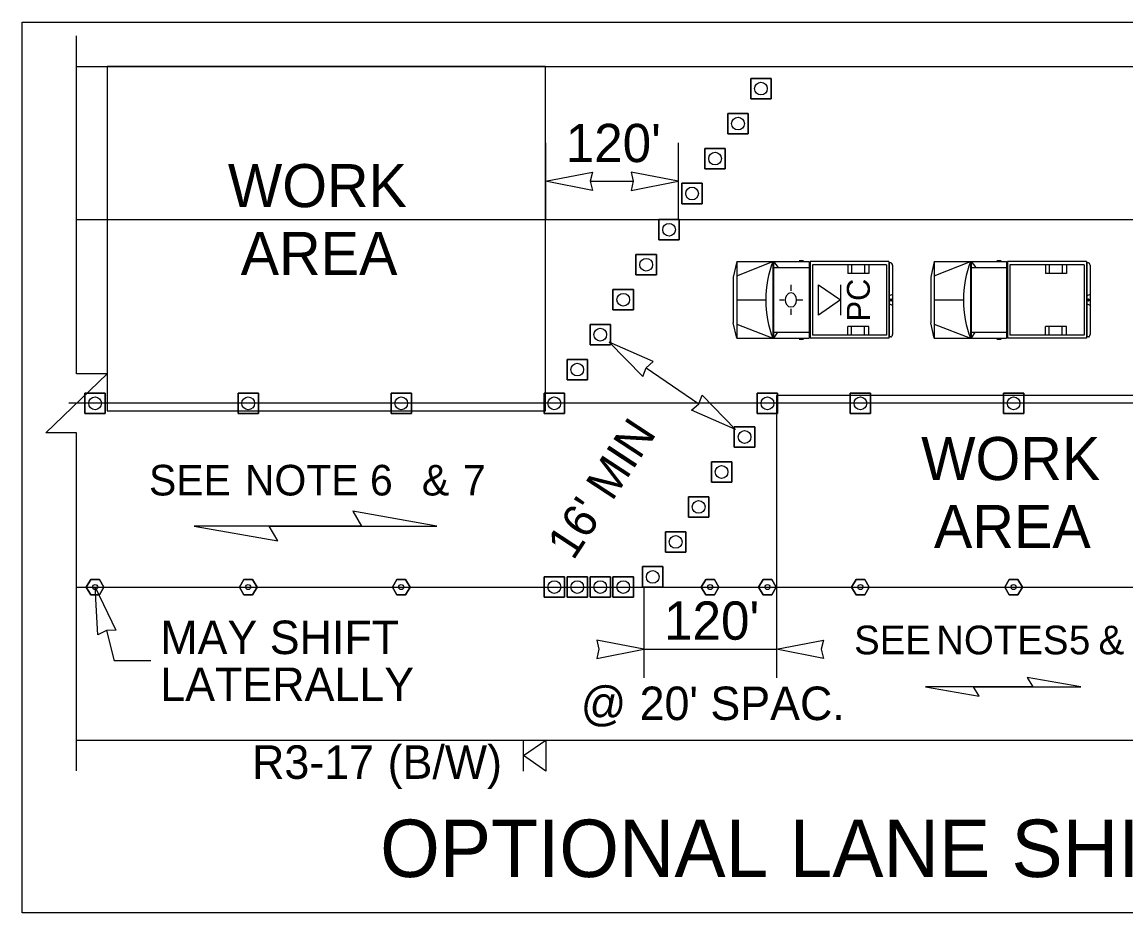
# Model space of a CAD drawing. Extents: x 99999.1 to 100095.7, y 99995 to 100010.7.
# Drawn here: x 100045.162 to 100047.47, y 100003.505 to 100005.366 of the extents above; entities that cross this region are included whole.
import ezdxf

# ---------------------------------------------------------------- set-up
doc = ezdxf.new("R2010")
doc.units = 0
for name, color, linetype in [('RD_ED_ShoulderPavedEdge', 7, 'Continuous'), ('RD_MK_LineEdgeWhite', 7, 'Continuous'), ('RD_MK_LineSkipCenter', 7, 'Continuous'), ('SH_DE_DetailHeading2Text', 7, 'Continuous'), ('SH_TI_Tables', 7, 'Continuous'), ('TR_WZ_MotoristVehicle', 7, 'Continuous'), ('TR_WZ_PortableSignMountBlk-Wht', 7, 'Continuous'), ('TR_WZ_TrafficCone', 7, 'Continuous'), ('TR_WZ_TubularMarker', 7, 'Continuous'), ('TR_WZ_WorkZoneDetails', 7, 'Continuous'), ('TR_WZ_WorkZoneTextCurrent', 7, 'Continuous')]:
    doc.layers.add(name, color=color, linetype=linetype)

msp = doc.modelspace()

# ---------------------------------------------------------------- linework, layer by layer
at = {"layer": 'RD_ED_ShoulderPavedEdge'}
for p, q in [((100045.2759, 100005.2735), (100049.1933, 100005.2735)), ((100045.2759, 100003.8655), (100049.1933, 100003.8655))]:
    msp.add_line(p, q, dxfattribs=at)
at = {"layer": 'RD_MK_LineEdgeWhite'}
for p, q in [((100045.2759, 100004.9535), (100049.1933, 100004.9535)), ((100045.2759, 100004.1855), (100049.1933, 100004.1855))]:
    msp.add_line(p, q, dxfattribs=at)
at = {"layer": 'RD_MK_LineSkipCenter'}
msp.add_lwpolyline([(100049.1767, 100004.5695), (100045.2594, 100004.5695)], dxfattribs=at)
at = {"layer": 'SH_TI_Tables'}
msp.add_lwpolyline([(100045.1619, 100005.3662), (100049.3073, 100005.3662), (100049.3073, 100003.5045), (100045.1619, 100003.5045)], close=True, dxfattribs=at)
at = {"layer": 'TR_WZ_MotoristVehicle'}
for p, q in [((100046.656, 100004.8655), (100046.6486, 100004.8332)), ((100046.656, 100004.8655), (100046.656, 100004.7055)), ((100046.656, 100004.8655), (100046.8071, 100004.8655)), ((100046.656, 100004.8362), (100046.7316, 100004.8655)), ((100046.7316, 100004.8655), (100046.7316, 100004.7055)), ((100046.7329, 100004.8655), (100046.7329, 100004.7055)), ((100046.7329, 100004.8655), (100046.7425, 100004.8531)), ((100046.7329, 100004.8531), (100046.8071, 100004.8531)), ((100046.7865, 100004.8677), (100046.7956, 100004.8677)), ((100046.8071, 100004.8655), (100046.8071, 100004.7055)), ((100046.9739, 100004.8655), (100046.8093, 100004.8655)), ((100046.8093, 100004.8655), (100046.8093, 100004.7055)), ((100046.9692, 100004.8591), (100046.814, 100004.8591)), ((100046.814, 100004.8591), (100046.814, 100004.7119)), ((100046.8882, 100004.8591), (100046.8882, 100004.8407)), ((100046.8961, 100004.8591), (100046.8961, 100004.8407)), ((100046.9233, 100004.8591), (100046.9233, 100004.8407)), ((100046.9321, 100004.8591), (100046.9321, 100004.8407)), ((100046.9692, 100004.8591), (100046.9692, 100004.7119)), ((100046.9739, 100004.8655), (100046.9739, 100004.7055)), ((100046.978, 100004.8629), (100046.9744, 100004.8629)), ((100046.9744, 100004.8629), (100046.9744, 100004.7081)), ((100046.9816, 100004.858), (100046.9816, 100004.713)), ((100047.069, 100004.8655), (100047.0616, 100004.8332)), ((100047.069, 100004.8655), (100047.069, 100004.7055)), ((100047.069, 100004.8655), (100047.2201, 100004.8655)), ((100047.069, 100004.8362), (100047.1446, 100004.8655)), ((100047.1446, 100004.8655), (100047.1446, 100004.7055)), ((100047.1459, 100004.8655), (100047.1459, 100004.7055)), ((100047.1459, 100004.8655), (100047.1556, 100004.8531)), ((100047.1459, 100004.8531), (100047.2201, 100004.8531)), ((100047.1995, 100004.8677), (100047.2086, 100004.8677)), ((100047.2201, 100004.8655), (100047.2201, 100004.7055)), ((100047.3869, 100004.8655), (100047.2223, 100004.8655)), ((100047.2223, 100004.8655), (100047.2223, 100004.7055)), ((100047.3822, 100004.8591), (100047.227, 100004.8591)), ((100047.227, 100004.8591), (100047.227, 100004.7119)), ((100047.3012, 100004.8591), (100047.3012, 100004.8407)), ((100047.3091, 100004.8591), (100047.3091, 100004.8407)), ((100047.3364, 100004.8591), (100047.3364, 100004.8407)), ((100047.3451, 100004.8591), (100047.3451, 100004.8407)), ((100047.3822, 100004.8591), (100047.3822, 100004.7119)), ((100047.3869, 100004.8655), (100047.3869, 100004.7055)), ((100047.391, 100004.8629), (100047.3875, 100004.8629)), ((100047.3875, 100004.8629), (100047.3875, 100004.7081)), ((100047.3946, 100004.858), (100047.3946, 100004.713)), ((100046.6486, 100004.8332), (100046.6486, 100004.7378)), ((100046.9321, 100004.8407), (100046.8882, 100004.8407)), ((100047.0616, 100004.8332), (100047.0616, 100004.7378)), ((100047.3451, 100004.8407), (100047.3012, 100004.8407)), ((100046.7692, 100004.8172), (100046.7692, 100004.8043)), ((100046.656, 100004.7855), (100046.7167, 100004.7855)), ((100046.7451, 100004.7856), (100046.7552, 100004.7856)), ((100046.7805, 100004.7852), (100046.7805, 100004.7852)), ((100046.7939, 100004.7849), (100046.782, 100004.7852)), ((100046.9816, 100004.7968), (100046.9744, 100004.7938)), ((100046.9797, 100004.7855), (100046.9764, 100004.7855)), ((100046.978, 100004.7877), (100046.978, 100004.7832)), ((100047.069, 100004.7855), (100047.1297, 100004.7855)), ((100047.3946, 100004.7968), (100047.3875, 100004.7938)), ((100047.3927, 100004.7855), (100047.3894, 100004.7855)), ((100047.391, 100004.7877), (100047.391, 100004.7832)), ((100046.7698, 100004.7547), (100046.7695, 100004.7668)), ((100046.9816, 100004.7742), (100046.9744, 100004.7772)), ((100047.3946, 100004.7742), (100047.3875, 100004.7772)), ((100046.656, 100004.7055), (100046.6486, 100004.7378)), ((100046.656, 100004.7348), (100046.7316, 100004.7055)), ((100047.069, 100004.7055), (100047.0616, 100004.7378)), ((100047.069, 100004.7348), (100047.1446, 100004.7055)), ((100046.7329, 100004.7179), (100046.8071, 100004.7179)), ((100046.7409, 100004.7179), (100046.7329, 100004.7055)), ((100046.9692, 100004.7119), (100046.814, 100004.7119)), ((100046.8882, 100004.7119), (100046.8882, 100004.7303)), ((100046.9321, 100004.7303), (100046.8882, 100004.7303)), ((100046.8961, 100004.7119), (100046.8961, 100004.7303)), ((100046.9233, 100004.7119), (100046.9233, 100004.7303)), ((100046.9321, 100004.7119), (100046.9321, 100004.7303)), ((100047.1459, 100004.7179), (100047.2201, 100004.7179)), ((100047.1539, 100004.7179), (100047.1459, 100004.7055)), ((100047.3822, 100004.7119), (100047.227, 100004.7119)), ((100047.3012, 100004.7119), (100047.3012, 100004.7303)), ((100047.3451, 100004.7303), (100047.3012, 100004.7303)), ((100047.3091, 100004.7119), (100047.3091, 100004.7303)), ((100047.3364, 100004.7119), (100047.3364, 100004.7303)), ((100047.3451, 100004.7119), (100047.3451, 100004.7303)), ((100046.656, 100004.7055), (100046.8071, 100004.7055)), ((100046.7865, 100004.7032), (100046.7956, 100004.7032)), ((100046.9739, 100004.7055), (100046.8093, 100004.7055)), ((100046.978, 100004.7081), (100046.9744, 100004.7081)), ((100047.069, 100004.7055), (100047.2201, 100004.7055)), ((100047.1995, 100004.7032), (100047.2086, 100004.7032)), ((100047.3869, 100004.7055), (100047.2223, 100004.7055)), ((100047.391, 100004.7081), (100047.3875, 100004.7081))]:
    msp.add_line(p, q, dxfattribs=at)
for centre, major_axis, start_param, end_param in [((100046.8395, 100004.7855), (0, -0.1679), 4.215667, 5.208926), ((100046.978, 100004.858), (0, 0.00488), 4.712389, 6.283185), ((100047.2526, 100004.7855), (0, -0.1679), 4.215667, 5.208926), ((100047.391, 100004.858), (0, 0.00488), 4.712389, 6.283185), ((100046.978, 100004.713), (0, -0.00488), 0, 1.570796), ((100047.391, 100004.713), (0, -0.00488), 0, 1.570796)]:
    msp.add_ellipse(centre, major_axis=major_axis, ratio=0.73155, start_param=start_param, end_param=end_param, dxfattribs=at)
for centre, major_axis in [((100046.7692, 100004.7855), (0, 0.0154)), ((100046.978, 100004.7855), (0, 0.00225)), ((100047.391, 100004.7855), (0, 0.00225))]:
    msp.add_ellipse(centre, major_axis=major_axis, ratio=0.73155, dxfattribs=at)
at = {"layer": 'TR_WZ_PortableSignMountBlk-Wht'}
for p, q in [((100046.8731, 100004.8174), (100046.8731, 100004.7534)), ((100046.2103, 100003.8011), (100046.2103, 100003.8655))]:
    msp.add_line(p, q, dxfattribs=at)
for points in [[(100046.8731, 100004.7855), (100046.8271, 100004.7534), (100046.8271, 100004.8174)], [(100046.2103, 100003.8333), (100046.2565, 100003.8655), (100046.2565, 100003.8011)]]:
    msp.add_lwpolyline(points, close=True, dxfattribs=at)
at = {"layer": 'TR_WZ_TrafficCone'}
for points in [[(100046.6853, 100005.2484), (100046.7279, 100005.2484), (100046.7279, 100005.2058), (100046.6853, 100005.2058), (100046.6853, 100005.2484)], [(100046.6853, 100005.2058), (100046.7279, 100005.2058), (100046.7279, 100005.2484), (100046.6853, 100005.2484), (100046.6853, 100005.2058)], [(100046.6373, 100005.1754), (100046.6799, 100005.1754), (100046.6799, 100005.1327), (100046.6373, 100005.1327), (100046.6373, 100005.1754)], [(100046.6373, 100005.1327), (100046.6799, 100005.1327), (100046.6799, 100005.1754), (100046.6373, 100005.1754), (100046.6373, 100005.1327)], [(100046.5893, 100005.1023), (100046.6319, 100005.1023), (100046.6319, 100005.0596), (100046.5893, 100005.0596), (100046.5893, 100005.1023)], [(100046.5893, 100005.0596), (100046.6319, 100005.0596), (100046.6319, 100005.1023), (100046.5893, 100005.1023), (100046.5893, 100005.0596)], [(100046.5413, 100005.0292), (100046.5839, 100005.0292), (100046.5839, 100004.9866), (100046.5413, 100004.9866), (100046.5413, 100005.0292)], [(100046.5413, 100004.9866), (100046.5839, 100004.9866), (100046.5839, 100005.0292), (100046.5413, 100005.0292), (100046.5413, 100004.9866)], [(100046.5359, 100004.9535), (100046.4932, 100004.9535), (100046.4932, 100004.9108), (100046.5359, 100004.9108), (100046.5359, 100004.9535)], [(100046.5359, 100004.9108), (100046.4932, 100004.9108), (100046.4932, 100004.9535), (100046.5359, 100004.9535), (100046.5359, 100004.9108)], [(100046.4879, 100004.8804), (100046.4452, 100004.8804), (100046.4452, 100004.8378), (100046.4879, 100004.8378), (100046.4879, 100004.8804)], [(100046.4879, 100004.8378), (100046.4452, 100004.8378), (100046.4452, 100004.8804), (100046.4879, 100004.8804), (100046.4879, 100004.8378)], [(100046.4399, 100004.8074), (100046.3972, 100004.8074), (100046.3972, 100004.7647), (100046.4399, 100004.7647), (100046.4399, 100004.8074)], [(100046.4399, 100004.7647), (100046.3972, 100004.7647), (100046.3972, 100004.8074), (100046.4399, 100004.8074), (100046.4399, 100004.7647)], [(100046.3919, 100004.7343), (100046.3492, 100004.7343), (100046.3492, 100004.6916), (100046.3919, 100004.6916), (100046.3919, 100004.7343)], [(100046.3919, 100004.6916), (100046.3492, 100004.6916), (100046.3492, 100004.7343), (100046.3919, 100004.7343), (100046.3919, 100004.6916)], [(100046.3439, 100004.6612), (100046.3012, 100004.6612), (100046.3012, 100004.6186), (100046.3439, 100004.6186), (100046.3439, 100004.6612)], [(100046.3439, 100004.6186), (100046.3012, 100004.6186), (100046.3012, 100004.6612), (100046.3439, 100004.6612), (100046.3439, 100004.6186)], [(100045.2933, 100004.5908), (100045.3359, 100004.5908), (100045.3359, 100004.5482), (100045.2933, 100004.5482), (100045.2933, 100004.5908)], [(100045.2933, 100004.5482), (100045.3359, 100004.5482), (100045.3359, 100004.5908), (100045.2933, 100004.5908), (100045.2933, 100004.5482)], [(100045.6133, 100004.5908), (100045.6559, 100004.5908), (100045.6559, 100004.5482), (100045.6133, 100004.5482), (100045.6133, 100004.5908)], [(100045.6133, 100004.5482), (100045.6559, 100004.5482), (100045.6559, 100004.5908), (100045.6133, 100004.5908), (100045.6133, 100004.5482)], [(100045.9333, 100004.5908), (100045.9759, 100004.5908), (100045.9759, 100004.5482), (100045.9333, 100004.5482), (100045.9333, 100004.5908)], [(100045.9333, 100004.5482), (100045.9759, 100004.5482), (100045.9759, 100004.5908), (100045.9333, 100004.5908), (100045.9333, 100004.5482)], [(100046.2959, 100004.5908), (100046.2532, 100004.5908), (100046.2532, 100004.5482), (100046.2959, 100004.5482), (100046.2959, 100004.5908)], [(100046.2959, 100004.5482), (100046.2532, 100004.5482), (100046.2532, 100004.5908), (100046.2959, 100004.5908), (100046.2959, 100004.5482)], [(100046.7415, 100004.5908), (100046.6989, 100004.5908), (100046.6989, 100004.5482), (100046.7415, 100004.5482), (100046.7415, 100004.5908)], [(100046.7415, 100004.5482), (100046.6989, 100004.5482), (100046.6989, 100004.5908), (100046.7415, 100004.5908), (100046.7415, 100004.5482)], [(100046.8933, 100004.5908), (100046.9359, 100004.5908), (100046.9359, 100004.5482), (100046.8933, 100004.5482), (100046.8933, 100004.5908)], [(100046.8933, 100004.5482), (100046.9359, 100004.5482), (100046.9359, 100004.5908), (100046.8933, 100004.5908), (100046.8933, 100004.5482)], [(100047.2133, 100004.5908), (100047.2559, 100004.5908), (100047.2559, 100004.5482), (100047.2133, 100004.5482), (100047.2133, 100004.5908)], [(100047.2133, 100004.5482), (100047.2559, 100004.5482), (100047.2559, 100004.5908), (100047.2133, 100004.5908), (100047.2133, 100004.5482)], [(100046.6509, 100004.4778), (100046.6936, 100004.4778), (100046.6936, 100004.5204), (100046.6509, 100004.5204), (100046.6509, 100004.4778)], [(100046.6509, 100004.5204), (100046.6936, 100004.5204), (100046.6936, 100004.4778), (100046.6509, 100004.4778), (100046.6509, 100004.5204)], [(100046.6029, 100004.4047), (100046.6456, 100004.4047), (100046.6456, 100004.4474), (100046.6029, 100004.4474), (100046.6029, 100004.4047)], [(100046.6029, 100004.4474), (100046.6456, 100004.4474), (100046.6456, 100004.4047), (100046.6029, 100004.4047), (100046.6029, 100004.4474)], [(100046.5549, 100004.3316), (100046.5976, 100004.3316), (100046.5976, 100004.3743), (100046.5549, 100004.3743), (100046.5549, 100004.3316)], [(100046.5549, 100004.3743), (100046.5976, 100004.3743), (100046.5976, 100004.3316), (100046.5549, 100004.3316), (100046.5549, 100004.3743)], [(100046.5069, 100004.2586), (100046.5496, 100004.2586), (100046.5496, 100004.3012), (100046.5069, 100004.3012), (100046.5069, 100004.2586)], [(100046.5069, 100004.3012), (100046.5496, 100004.3012), (100046.5496, 100004.2586), (100046.5069, 100004.2586), (100046.5069, 100004.3012)], [(100046.4589, 100004.1855), (100046.5016, 100004.1855), (100046.5016, 100004.2282), (100046.4589, 100004.2282), (100046.4589, 100004.1855)], [(100046.4589, 100004.2282), (100046.5016, 100004.2282), (100046.5016, 100004.1855), (100046.4589, 100004.1855), (100046.4589, 100004.2282)], [(100046.2959, 100004.2068), (100046.2532, 100004.2068), (100046.2532, 100004.1642), (100046.2959, 100004.1642), (100046.2959, 100004.2068)], [(100046.2959, 100004.1642), (100046.2532, 100004.1642), (100046.2532, 100004.2068), (100046.2959, 100004.2068), (100046.2959, 100004.1642)], [(100046.3439, 100004.2068), (100046.3012, 100004.2068), (100046.3012, 100004.1642), (100046.3439, 100004.1642), (100046.3439, 100004.2068)], [(100046.3439, 100004.1642), (100046.3012, 100004.1642), (100046.3012, 100004.2068), (100046.3439, 100004.2068), (100046.3439, 100004.1642)], [(100046.3919, 100004.2068), (100046.3492, 100004.2068), (100046.3492, 100004.1642), (100046.3919, 100004.1642), (100046.3919, 100004.2068)], [(100046.3919, 100004.1642), (100046.3492, 100004.1642), (100046.3492, 100004.2068), (100046.3919, 100004.2068), (100046.3919, 100004.1642)], [(100046.4399, 100004.2068), (100046.3972, 100004.2068), (100046.3972, 100004.1642), (100046.4399, 100004.1642), (100046.4399, 100004.2068)], [(100046.4399, 100004.1642), (100046.3972, 100004.1642), (100046.3972, 100004.2068), (100046.4399, 100004.2068), (100046.4399, 100004.1642)]]:
    msp.add_lwpolyline(points, dxfattribs=at)
for centre in [(100046.7066, 100005.2271), (100046.6586, 100005.154), (100046.6106, 100005.081), (100046.5626, 100005.0079), (100046.5146, 100004.9322), (100046.4666, 100004.8591), (100046.4186, 100004.786), (100046.3706, 100004.713), (100046.3226, 100004.6399), (100045.3146, 100004.5695), (100045.6346, 100004.5695), (100045.9546, 100004.5695), (100046.2746, 100004.5695), (100046.7202, 100004.5695), (100046.9146, 100004.5695), (100047.2346, 100004.5695), (100046.6723, 100004.4991), (100046.6243, 100004.426), (100046.5763, 100004.353), (100046.5283, 100004.2799), (100046.4803, 100004.2068), (100046.2746, 100004.1855), (100046.3226, 100004.1855), (100046.3706, 100004.1855), (100046.4186, 100004.1855)]:
    msp.add_circle(centre, 0.0133, dxfattribs=at)
at = {"layer": 'TR_WZ_TubularMarker'}
for points in [[(100045.2961, 100004.1855), (100045.3054, 100004.2015), (100045.3239, 100004.2015), (100045.3331, 100004.1855), (100045.3239, 100004.1695), (100045.3054, 100004.1695)], [(100045.6161, 100004.1855), (100045.6254, 100004.2015), (100045.6438, 100004.2015), (100045.6531, 100004.1855), (100045.6438, 100004.1695), (100045.6254, 100004.1695)], [(100045.9361, 100004.1855), (100045.9454, 100004.2015), (100045.9638, 100004.2015), (100045.9731, 100004.1855), (100045.9638, 100004.1695), (100045.9454, 100004.1695)], [(100046.6187, 100004.1855), (100046.6095, 100004.2015), (100046.591, 100004.2015), (100046.5818, 100004.1855), (100046.591, 100004.1695), (100046.6095, 100004.1695)], [(100046.7387, 100004.1855), (100046.7294, 100004.2015), (100046.711, 100004.2015), (100046.7017, 100004.1855), (100046.711, 100004.1695), (100046.7294, 100004.1695)], [(100046.9331, 100004.1855), (100046.9238, 100004.2015), (100046.9054, 100004.2015), (100046.8961, 100004.1855), (100046.9054, 100004.1695), (100046.9238, 100004.1695)], [(100047.2531, 100004.1855), (100047.2438, 100004.2015), (100047.2254, 100004.2015), (100047.2161, 100004.1855), (100047.2254, 100004.1695), (100047.2438, 100004.1695)]]:
    msp.add_lwpolyline(points, close=True, dxfattribs=at)
for points in [[(100045.3054, 100004.1695), (100045.3239, 100004.1695), (100045.3331, 100004.1855), (100045.3239, 100004.2015), (100045.3054, 100004.2015), (100045.2961, 100004.1855), (100045.3054, 100004.1695)], [(100045.6254, 100004.1695), (100045.6438, 100004.1695), (100045.6531, 100004.1855), (100045.6438, 100004.2015), (100045.6254, 100004.2015), (100045.6161, 100004.1855), (100045.6254, 100004.1695)], [(100045.9454, 100004.1695), (100045.9638, 100004.1695), (100045.9731, 100004.1855), (100045.9638, 100004.2015), (100045.9454, 100004.2015), (100045.9361, 100004.1855), (100045.9454, 100004.1695)], [(100046.6095, 100004.1695), (100046.591, 100004.1695), (100046.5818, 100004.1855), (100046.591, 100004.2015), (100046.6095, 100004.2015), (100046.6187, 100004.1855), (100046.6095, 100004.1695)], [(100046.7294, 100004.1695), (100046.711, 100004.1695), (100046.7017, 100004.1855), (100046.711, 100004.2015), (100046.7294, 100004.2015), (100046.7387, 100004.1855), (100046.7294, 100004.1695)], [(100046.9238, 100004.1695), (100046.9054, 100004.1695), (100046.8961, 100004.1855), (100046.9054, 100004.2015), (100046.9238, 100004.2015), (100046.9331, 100004.1855), (100046.9238, 100004.1695)], [(100047.2438, 100004.1695), (100047.2254, 100004.1695), (100047.2161, 100004.1855), (100047.2254, 100004.2015), (100047.2438, 100004.2015), (100047.2531, 100004.1855), (100047.2438, 100004.1695)]]:
    msp.add_lwpolyline(points, dxfattribs=at)
for centre in [(100045.3146, 100004.1855), (100045.6346, 100004.1855), (100045.9546, 100004.1855), (100046.6002, 100004.1855), (100046.7202, 100004.1855), (100046.9146, 100004.1855), (100047.2346, 100004.1855)]:
    msp.add_circle(centre, 0.00533, dxfattribs=at)
at = {"layer": 'TR_WZ_WorkZoneDetails'}
for p, q in [((100046.2559, 100005.1135), (100046.2559, 100004.9535)), ((100046.5333, 100005.1135), (100046.5333, 100004.9535)), ((100046.3497, 100005.0335), (100046.4395, 100005.0335)), ((100046.4665, 100004.6438), (100046.5764, 100004.5682)), ((100045.6787, 100004.3129), (100045.8716, 100004.3129)), ((100045.8716, 100004.3129), (100045.6787, 100004.3129)), ((100046.4616, 100004.1855), (100046.4616, 100003.9955)), ((100046.7389, 100004.1855), (100046.7389, 100003.9955)), ((100045.3382, 100004.0948), (100045.3546, 100004.0314)), ((100046.4616, 100004.0555), (100046.7389, 100004.0555)), ((100045.4308, 100004.0314), (100045.3546, 100004.0314)), ((100047.2746, 100003.9769), (100047.1512, 100003.9769)), ((100047.1512, 100003.9769), (100047.2746, 100003.9769))]:
    msp.add_line(p, q, dxfattribs=at)
msp.add_lwpolyline([(100045.2759, 100003.8015), (100045.2759, 100004.5075), (100045.2119, 100004.5075), (100045.3399, 100004.6314), (100045.2759, 100004.6314), (100045.2759, 100005.3375)], dxfattribs=at)
for points in [[(100045.3399, 100005.2735), (100045.3399, 100004.5535), (100046.2559, 100004.5535), (100046.2559, 100005.2735)], [(100046.2559, 100005.0335), (100046.3542, 100005.0528), (100046.3497, 100005.0335), (100046.3542, 100005.0142)], [(100046.5333, 100005.0335), (100046.435, 100005.0528), (100046.4395, 100005.0335), (100046.435, 100005.0142)], [(100046.3893, 100004.697), (100046.4593, 100004.6254), (100046.4665, 100004.6438), (100046.4811, 100004.6571)], [(100046.6536, 100004.5151), (100046.5617, 100004.5549), (100046.5764, 100004.5682), (100046.5835, 100004.5867)], [(100046.7389, 100004.5855), (100046.7389, 100004.1855), (100047.7173, 100004.1855), (100047.7173, 100004.5855)], [(100046.0288, 100004.3129), (100045.8537, 100004.3438), (100045.8716, 100004.3129)], [(100045.5214, 100004.3129), (100045.6965, 100004.2821), (100045.6787, 100004.3129)], [(100045.3146, 100004.1855), (100045.3579, 100004.0952), (100045.3381, 100004.0948), (100045.3206, 100004.0855)], [(100046.4616, 100004.0555), (100046.3633, 100004.0748), (100046.3678, 100004.0555), (100046.3633, 100004.0362)], [(100046.7389, 100004.0555), (100046.8372, 100004.0748), (100046.8326, 100004.0555), (100046.8372, 100004.0362)], [(100047.3753, 100003.9769), (100047.2632, 100003.9967), (100047.2746, 100003.9769)], [(100047.0506, 100003.9769), (100047.1626, 100003.9572), (100047.1512, 100003.9769)]]:
    msp.add_lwpolyline(points, close=True, dxfattribs=at)

# ---------------------------------------------------------------- texts
at = {"layer": 'SH_DE_DetailHeading2Text'}
msp.add_text('OPTIONAL LANE SHIFT DETAIL', height=0.12, rotation=360, dxfattribs=at).set_placement((100045.9105, 100003.5795))
at = {"layer": 'TR_WZ_MotoristVehicle'}
msp.add_text('PC', height=0.048, rotation=90, dxfattribs=at).set_placement((100046.9342, 100004.7407))
at = {"layer": 'TR_WZ_WorkZoneDetails'}
for s, p in [('WORK', (100045.5922, 100004.9794)), ('AREA', (100045.6189, 100004.8376)), ('WORK', (100047.0415, 100004.4091)), ('AREA', (100047.0682, 100004.2672))]:
    msp.add_text(s, height=0.09, dxfattribs=at).set_placement(p)
for s, p in [('(B/W)', (100045.9261, 100003.7847)), ('R3-17', (100045.6427, 100003.7847))]:
    msp.add_text(s, height=0.07, rotation=360, dxfattribs=at).set_placement(p)
at = {"layer": 'TR_WZ_WorkZoneTextCurrent'}
for s, height, rotation, p in [("120'", 0.08, 360, (100046.2985, 100005.0735)), ("16' MIN", 0.07, 56.6977, (100046.3141, 100004.2393)), ("120'", 0.08, 360, (100046.5041, 100004.0755)), ('@', 0.07, 360, (100046.33, 100003.9075)), ("20' SPAC.", 0.07, 360, (100046.4529, 100003.9075))]:
    msp.add_text(s, height=height, rotation=rotation, dxfattribs=at).set_placement(p)
for s, height, p in [('SEE', 0.064, (100045.4272, 100004.3769)), ('NOTE 6', 0.064, (100045.6277, 100004.3769)), ('&', 0.064, (100045.9978, 100004.3769)), ('7', 0.064, (100046.0836, 100004.3769)), ('MAY SHIFT', 0.07, (100045.4508, 100004.0454)), ('SEE', 0.06, (100046.9013, 100004.0449)), ('NOTES', 0.06, (100047.073, 100004.0449)), ('5', 0.06, (100047.3505, 100004.0449)), ('&', 0.06, (100047.4123, 100004.0449)), ('LATERALLY', 0.07, (100045.4508, 100003.9474))]:
    msp.add_text(s, height=height, dxfattribs=at).set_placement(p)

doc.saveas('drawing.dxf')
